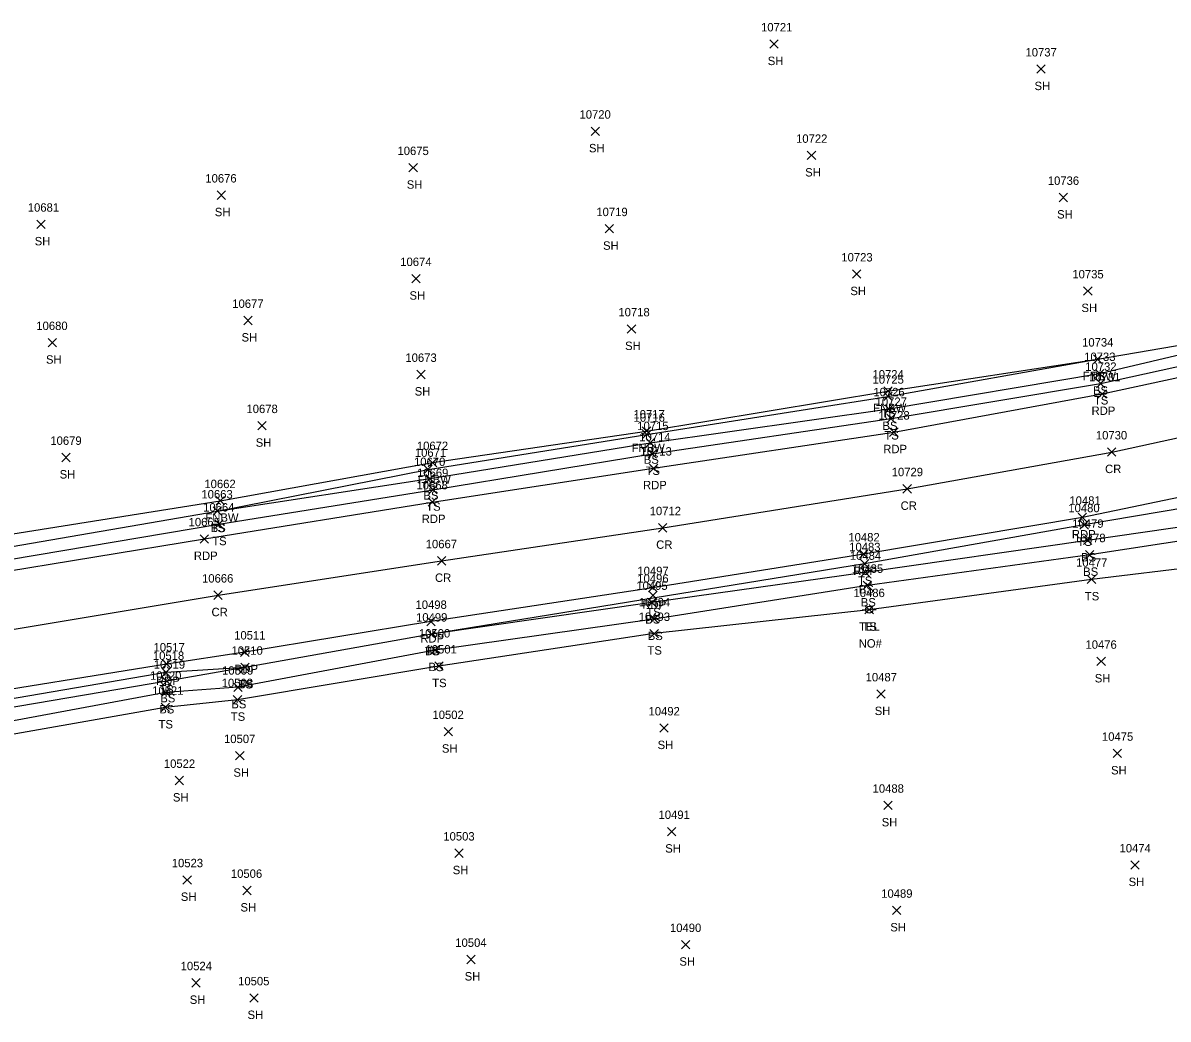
# Model space of a CAD drawing. Extents: x 1475671 to 1477951, y 592661 to 593821.
# Drawn here: x 1476066.9 to 1476339, y 592892.8 to 593129.6 of the extents above; entities that cross this region are included whole.
import ezdxf

# ---------------------------------------------------------------- set-up
doc = ezdxf.new("R2010")
doc.units = 0
for name, color, linetype in [('L_A', 7, 'Continuous'), ('L_I', 7, 'Continuous'), ('L_TIC', 7, 'Continuous'), ('LELB', 7, 'Continuous'), ('LFNC', 7, 'Continuous'), ('P_A', 7, 'Continuous'), ('P_I', 7, 'Continuous'), ('P_TIC', 7, 'Continuous'), ('PET', 7, 'Continuous'), ('PRC', 7, 'Continuous'), ('U_A', 7, 'Continuous'), ('U_C', 7, 'Continuous'), ('U_I', 7, 'Continuous'), ('UP', 7, 'Continuous')]:
    doc.layers.add(name, color=color, linetype=linetype)

msp = doc.modelspace()

# ---------------------------------------------------------------- linework, layer by layer
at = {"layer": 'L_TIC'}
for points in [[(1476244.39, 593123.56), (1476246.39, 593125.56)], [(1476246.39, 593123.56), (1476244.39, 593125.56)], [(1476307.77, 593117.61), (1476309.77, 593119.61)], [(1476309.77, 593117.61), (1476307.77, 593119.61)], [(1476201.91, 593102.83), (1476203.91, 593104.83)], [(1476203.91, 593102.83), (1476201.91, 593104.83)], [(1476253.28, 593097.09), (1476255.28, 593099.09)], [(1476255.28, 593097.09), (1476253.28, 593099.09)], [(1476158.63, 593094.18), (1476160.63, 593096.18)], [(1476160.63, 593094.18), (1476158.63, 593096.18)], [(1476113.04, 593087.65), (1476115.04, 593089.65)], [(1476115.04, 593087.65), (1476113.04, 593089.65)], [(1476313.13, 593087.1), (1476315.13, 593089.1)], [(1476315.13, 593087.1), (1476313.13, 593089.1)], [(1476070.23, 593080.72), (1476072.23, 593082.72)], [(1476072.23, 593080.72), (1476070.23, 593082.72)], [(1476205.27, 593079.67), (1476207.27, 593081.67)], [(1476207.27, 593079.67), (1476205.27, 593081.67)], [(1476159.29, 593067.81), (1476161.29, 593069.81)], [(1476161.29, 593067.81), (1476159.29, 593069.81)], [(1476264.02, 593068.89), (1476266.02, 593070.89)], [(1476266.02, 593068.89), (1476264.02, 593070.89)], [(1476318.92, 593064.87), (1476320.92, 593066.87)], [(1476320.92, 593064.87), (1476318.92, 593066.87)], [(1476119.38, 593057.86), (1476121.38, 593059.86)], [(1476121.38, 593057.86), (1476119.38, 593059.86)], [(1476210.5, 593055.85), (1476212.5, 593057.85)], [(1476212.5, 593055.85), (1476210.5, 593057.85)], [(1476072.92, 593052.6), (1476074.92, 593054.6)], [(1476074.92, 593052.6), (1476072.92, 593054.6)], [(1476321.23, 593048.67), (1476323.23, 593050.67)], [(1476323.23, 593048.67), (1476321.23, 593050.67)], [(1476321.23, 593048.67), (1476323.23, 593050.67)], [(1476323.23, 593048.67), (1476321.23, 593050.67)], [(1476160.51, 593045.03), (1476162.51, 593047.03)], [(1476162.51, 593045.03), (1476160.51, 593047.03)], [(1476321.72, 593045.24), (1476323.72, 593047.24)], [(1476323.72, 593045.24), (1476321.72, 593047.24)], [(1476321.97, 593042.9), (1476323.97, 593044.9)], [(1476323.97, 593042.9), (1476321.97, 593044.9)], [(1476271.43, 593041.08), (1476273.43, 593043.08)], [(1476273.43, 593041.08), (1476271.43, 593043.08)], [(1476271.44, 593039.84), (1476273.44, 593041.84)], [(1476273.44, 593039.84), (1476271.44, 593041.84)], [(1476271.69, 593036.85), (1476273.69, 593038.85)], [(1476273.69, 593036.85), (1476271.69, 593038.85)], [(1476272.17, 593034.57), (1476274.17, 593036.57)], [(1476274.17, 593034.57), (1476272.17, 593036.57)], [(1476122.74, 593032.86), (1476124.74, 593034.86)], [(1476124.74, 593032.86), (1476122.74, 593034.86)], [(1476214.07, 593031.59), (1476216.07, 593033.59)], [(1476216.07, 593031.59), (1476214.07, 593033.59)], [(1476214.16, 593030.8), (1476216.16, 593032.8)], [(1476216.16, 593030.8), (1476214.16, 593032.8)], [(1476214.98, 593028.82), (1476216.98, 593030.82)], [(1476216.98, 593028.82), (1476214.98, 593030.82)], [(1476215.45, 593026.16), (1476217.45, 593028.16)], [(1476217.45, 593026.16), (1476215.45, 593028.16)], [(1476076.16, 593025.31), (1476078.16, 593027.31)], [(1476078.16, 593025.31), (1476076.16, 593027.31)], [(1476163.23, 593024.08), (1476165.23, 593026.08)], [(1476165.23, 593024.08), (1476163.23, 593026.08)], [(1476162.19, 593022.46), (1476164.19, 593024.46)], [(1476164.19, 593022.46), (1476162.19, 593024.46)], [(1476162.64, 593020.28), (1476164.64, 593022.28)], [(1476164.64, 593020.28), (1476162.64, 593022.28)], [(1476163.33, 593017.66), (1476165.33, 593019.66)], [(1476165.33, 593017.66), (1476163.33, 593019.66)], [(1476112.81, 593015.03), (1476114.81, 593017.03)], [(1476114.81, 593015.03), (1476112.81, 593017.03)], [(1476112.1, 593012.57), (1476114.1, 593014.57)], [(1476114.1, 593012.57), (1476112.1, 593014.57)], [(1476112.1, 593012.57), (1476114.1, 593014.57)], [(1476114.1, 593012.57), (1476112.1, 593014.57)], [(1476112.5, 593009.46), (1476114.5, 593011.46)], [(1476114.5, 593009.46), (1476112.5, 593011.46)], [(1476318.05, 593009.3), (1476320.05, 593011.3)], [(1476320.05, 593009.3), (1476318.05, 593011.3)], [(1476318.88, 593005.6), (1476320.88, 593007.6)], [(1476320.88, 593005.6), (1476318.88, 593007.6)], [(1476319.37, 593002.18), (1476321.37, 593004.18)], [(1476321.37, 593002.18), (1476319.37, 593004.18)], [(1476265.9, 593000.04), (1476267.9, 593002.04)], [(1476267.9, 593000.04), (1476265.9, 593002.04)], [(1476266.05, 592997.99), (1476268.05, 592999.99)], [(1476268.05, 592997.99), (1476266.05, 592999.99)], [(1476319.8, 592996.35), (1476321.8, 592998.35)], [(1476321.8, 592996.35), (1476319.8, 592998.35)], [(1476266.54, 592994.9), (1476268.54, 592996.9)], [(1476268.54, 592994.9), (1476266.54, 592996.9)], [(1476215.33, 592990.85), (1476217.33, 592992.85)], [(1476217.33, 592990.85), (1476215.33, 592992.85)], [(1476215.62, 592992.55), (1476217.62, 592994.55)], [(1476217.62, 592992.55), (1476215.62, 592994.55)], [(1476266.98, 592989.13), (1476268.98, 592991.13)], [(1476268.98, 592989.13), (1476266.98, 592991.13)], [(1476215.93, 592986.92), (1476217.93, 592988.92)], [(1476217.93, 592986.92), (1476215.93, 592988.92)], [(1476163.01, 592983.31), (1476165.01, 592985.31)], [(1476165.01, 592983.31), (1476163.01, 592985.31)], [(1476163.01, 592983.31), (1476165.01, 592985.31)], [(1476165.01, 592983.31), (1476163.01, 592985.31)], [(1476215.9, 592983.46), (1476217.9, 592985.46)], [(1476217.9, 592983.46), (1476215.9, 592985.46)], [(1476163.84, 592979.53), (1476165.84, 592981.53)], [(1476165.84, 592979.53), (1476163.84, 592981.53)], [(1476322.08, 592976.85), (1476324.08, 592978.85)], [(1476324.08, 592976.85), (1476322.08, 592978.85)], [(1476099.91, 592974.21), (1476101.91, 592976.21)], [(1476101.91, 592974.21), (1476099.91, 592976.21)], [(1476118.67, 592975.43), (1476120.67, 592977.43)], [(1476120.67, 592975.43), (1476118.67, 592977.43)], [(1476118.67, 592975.43), (1476120.67, 592977.43)], [(1476120.67, 592975.43), (1476118.67, 592977.43)], [(1476164.76, 592975.73), (1476166.76, 592977.73)], [(1476166.76, 592975.73), (1476164.76, 592977.73)], [(1476100.12, 592972.12), (1476102.12, 592974.12)], [(1476102.12, 592972.12), (1476100.12, 592974.12)], [(1476099.88, 592969.48), (1476101.88, 592971.48)], [(1476101.88, 592969.48), (1476099.88, 592971.48)], [(1476117, 592970.7), (1476119, 592972.7)], [(1476119, 592970.7), (1476117, 592972.7)], [(1476269.8, 592969.1), (1476271.8, 592971.1)], [(1476271.8, 592969.1), (1476269.8, 592971.1)], [(1476099.74, 592965.91), (1476101.74, 592967.91)], [(1476101.74, 592965.91), (1476099.74, 592967.91)], [(1476116.9, 592967.73), (1476118.9, 592969.73)], [(1476118.9, 592967.73), (1476116.9, 592969.73)], [(1476166.97, 592960.16), (1476168.97, 592962.16)], [(1476168.97, 592960.16), (1476166.97, 592962.16)], [(1476218.22, 592961.01), (1476220.22, 592963.01)], [(1476220.22, 592961.01), (1476218.22, 592963.01)], [(1476325.95, 592954.99), (1476327.95, 592956.99)], [(1476327.95, 592954.99), (1476325.95, 592956.99)], [(1476117.45, 592954.44), (1476119.45, 592956.44)], [(1476119.45, 592954.44), (1476117.45, 592956.44)], [(1476103.07, 592948.55), (1476105.07, 592950.55)], [(1476105.07, 592948.55), (1476103.07, 592950.55)], [(1476271.46, 592942.64), (1476273.46, 592944.64)], [(1476273.46, 592942.64), (1476271.46, 592944.64)], [(1476220.03, 592936.41), (1476222.03, 592938.41)], [(1476222.03, 592936.41), (1476220.03, 592938.41)], [(1476169.55, 592931.28), (1476171.55, 592933.28)], [(1476171.55, 592931.28), (1476169.55, 592933.28)], [(1476330.12, 592928.46), (1476332.12, 592930.46)], [(1476332.12, 592928.46), (1476330.12, 592930.46)], [(1476104.95, 592924.93), (1476106.95, 592926.93)], [(1476106.95, 592924.93), (1476104.95, 592926.93)], [(1476119.14, 592922.41), (1476121.14, 592924.41)], [(1476121.14, 592922.41), (1476119.14, 592924.41)], [(1476273.5, 592917.68), (1476275.5, 592919.68)], [(1476275.5, 592917.68), (1476273.5, 592919.68)], [(1476223.4, 592909.54), (1476225.4, 592911.54)], [(1476225.4, 592909.54), (1476223.4, 592911.54)], [(1476172.39, 592906.01), (1476174.39, 592908.01)], [(1476174.39, 592906.01), (1476172.39, 592908.01)], [(1476107.07, 592900.46), (1476109.07, 592902.46)], [(1476109.07, 592900.46), (1476107.07, 592902.46)], [(1476120.8, 592896.87), (1476122.8, 592898.87)], [(1476122.8, 592896.87), (1476120.8, 592898.87)]]:
    msp.add_lwpolyline(points, dxfattribs=at)
at = {"layer": 'LELB'}
for points in [[(1475681.97, 592926.29), (1475693.99, 592930.92), (1475717.71, 592935.95), (1475764.49, 592948.74), (1475792.84, 592955.38), (1475826.76, 592965.2), (1475839.14, 592967.57), (1475847.44, 592968.45), (1475896, 592975.83), (1475948.75, 592985.5), (1475992.67, 592993.57), (1476057.44, 593003.96), (1476113.1, 593013.57), (1476163.64, 593021.28), (1476215.98, 593029.82), (1476272.69, 593037.85), (1476322.72, 593046.24), (1476372.45, 593058.02), (1476374.59, 593060.62), (1476398.56, 593065.83), (1476415.47, 593071.31), (1476457.34, 593084.84)], [(1476656.72, 593061.12), (1476648.18, 593059.88), (1476630.02, 593056.59), (1476594.66, 593048.99), (1476557.23, 593045.74), (1476521.08, 593042.35), (1476462.84, 593033.95), (1476419.94, 593027.86), (1476367.81, 593018.54), (1476319.05, 593010.3), (1476266.9, 593001.04), (1476164.01, 592984.31)], [(1475681.68, 592929.89), (1475693.99, 592930.92), (1475717.95, 592934.41), (1475766.45, 592946.03), (1475793.6, 592952.64), (1475827.75, 592961.96), (1475839.66, 592963.32), (1475897.61, 592972.89), (1475949.51, 592982.21), (1475996.32, 592990.67), (1476057.58, 593001.03), (1476113.5, 593010.46), (1476164.33, 593018.66), (1476216.45, 593027.16), (1476273.17, 593035.57), (1476322.97, 593043.9), (1476372.64, 593054.79), (1476374.63, 593058.12)], [(1476113.1, 593013.57), (1476163.19, 593023.46), (1476215.16, 593031.8), (1476272.44, 593040.84), (1476322.23, 593049.67)], [(1476521.14, 593041.18), (1476464.22, 593030.64), (1476420.77, 593020.64), (1476368.55, 593014.29), (1476359.82, 593012.38), (1476319.88, 593006.6), (1476267.05, 592998.99), (1476216.33, 592991.85), (1476164.01, 592984.31), (1476119.67, 592976.43), (1476101.12, 592973.12), (1476050.25, 592964.51), (1475994.64, 592956.24), (1475948.73, 592947.98), (1475899.49, 592939.5), (1475855.9, 592931.1), (1475802.57, 592920.15), (1475791.75, 592916.74), (1475792.51, 592914.78)], [(1476534.65, 593028.56), (1476525.69, 593019.5), (1476511.54, 593017.85), (1476467.31, 593015.01), (1476422.73, 593008.46), (1476366.85, 593001.28), (1476356.63, 592997.77), (1476347.04, 593000.45), (1476320.8, 592997.35), (1476267.98, 592990.13), (1476216.9, 592984.46), (1476165.76, 592976.73), (1476117.9, 592968.73), (1476100.74, 592966.91), (1476051.72, 592958.25), (1475996.01, 592950.36), (1475948.39, 592939), (1475900.82, 592931.75), (1475857.92, 592923.91), (1475803.59, 592912.34), (1475790.59, 592904.71)], [(1476511.04, 593028.14), (1476465.56, 593023.07), (1476421.22, 593014.7), (1476366.44, 593009.67), (1476355.54, 593008.55), (1476320.37, 593003.18), (1476267.54, 592995.9), (1476216.93, 592987.92), (1476164.84, 592980.53), (1476118, 592971.7), (1476100.88, 592970.48), (1476050.95, 592961.21), (1475995.34, 592954.17), (1475949.24, 592944.73), (1475901.01, 592937.79), (1475856.17, 592929.37), (1475802.39, 592917.73), (1475792.51, 592914.78)], [(1476119.67, 592976.43), (1476100.91, 592975.21), (1476049.54, 592966.45), (1475994.72, 592957.82), (1475948.15, 592950.07), (1475899.13, 592941.1), (1475855.65, 592932.47), (1475802.49, 592921.46), (1475788.48, 592918.16)]]:
    msp.add_lwpolyline(points, dxfattribs=at)
at = {"layer": 'LFNC'}
msp.add_lwpolyline([(1475680.63, 592937.28), (1475715.61, 592943.34), (1475763.84, 592955.14), (1475791.92, 592961.08), (1475824.89, 592967.76), (1475839.13, 592970.46), (1475847.47, 592971.97), (1475895.02, 592980.45), (1475948.31, 592989.25), (1475993.78, 592996.67), (1476056.99, 593006.94), (1476113.81, 593016.03), (1476164.23, 593025.08), (1476215.07, 593032.59), (1476272.43, 593042.08), (1476322.23, 593049.67), (1476368.09, 593057.49), (1476372.45, 593058.02), (1476374.63, 593058.12), (1476399.83, 593064.01), (1476415.89, 593069.22), (1476458.99, 593083.01), (1476499.73, 593099.84)], dxfattribs=at)
at = {"layer": 'P_TIC'}
for points in [[(1476322.32, 593040.42), (1476324.32, 593042.42)], [(1476324.32, 593040.42), (1476322.32, 593042.42)], [(1476272.83, 593031.32), (1476274.83, 593033.32)], [(1476274.83, 593031.32), (1476272.83, 593033.32)], [(1476324.59, 593026.6), (1476326.59, 593028.6)], [(1476326.59, 593026.6), (1476324.59, 593028.6)], [(1476215.75, 593022.76), (1476217.75, 593024.76)], [(1476217.75, 593022.76), (1476215.75, 593024.76)], [(1476276, 593017.86), (1476278, 593019.86)], [(1476278, 593017.86), (1476276, 593019.86)], [(1476163.18, 593014.73), (1476165.18, 593016.73)], [(1476165.18, 593014.73), (1476163.18, 593016.73)], [(1476317.64, 593011.07), (1476319.64, 593013.07)], [(1476319.64, 593011.07), (1476317.64, 593013.07)], [(1476217.93, 593008.6), (1476219.93, 593010.6)], [(1476219.93, 593008.6), (1476217.93, 593010.6)], [(1476109.05, 593005.96), (1476111.05, 593007.96)], [(1476111.05, 593005.96), (1476109.05, 593007.96)], [(1476265.69, 593002.36), (1476267.69, 593004.36)], [(1476267.69, 593002.36), (1476265.69, 593004.36)], [(1476165.39, 593000.74), (1476167.39, 593002.74)], [(1476167.39, 593000.74), (1476165.39, 593002.74)], [(1476215.58, 592994.35), (1476217.58, 592996.35)], [(1476217.58, 592994.35), (1476215.58, 592996.35)], [(1476112.3, 592992.58), (1476114.3, 592994.58)], [(1476114.3, 592992.58), (1476112.3, 592994.58)], [(1476162.86, 592986.33), (1476164.86, 592988.33)], [(1476164.86, 592986.33), (1476162.86, 592988.33)], [(1476118.65, 592979.05), (1476120.65, 592981.05)], [(1476120.65, 592979.05), (1476118.65, 592981.05)], [(1476100.05, 592976.22), (1476102.05, 592978.22)], [(1476102.05, 592976.22), (1476100.05, 592978.22)]]:
    msp.add_lwpolyline(points, dxfattribs=at)
at = {"layer": 'PET'}
for points in [[(1475682.06, 592924.71), (1475717.58, 592931.68), (1475766.32, 592943.31), (1475794.98, 592949.79), (1475825.77, 592956.33), (1475844.1, 592960.26), (1475899.54, 592970.95), (1475949.72, 592980.21), (1475996.45, 592988.43), (1476057.84, 592998.4), (1476110.05, 593006.96), (1476164.18, 593015.73), (1476216.75, 593023.76), (1476273.83, 593032.32), (1476323.32, 593041.42), (1476373.65, 593052.29), (1476409.24, 593061.35), (1476416.16, 593063.9), (1476459.25, 593078.48), (1476508.39, 593100.17)], [(1476521.33, 593044.37), (1476462.5, 593038.2), (1476408.69, 593032.05), (1476367.34, 593022.2), (1476318.64, 593012.07), (1476266.69, 593003.36), (1476216.58, 592995.35), (1476163.86, 592987.33), (1476119.65, 592980.05), (1476101.05, 592977.22), (1476048.95, 592968.83), (1475997.04, 592960.32), (1475947.8, 592951.63), (1475898.72, 592942.8), (1475855.26, 592933.74), (1475801.94, 592923.33), (1475788.88, 592919.68), (1475771.17, 592916.5), (1475722.69, 592905.51), (1475685.82, 592897.63)]]:
    msp.add_lwpolyline(points, dxfattribs=at)
at = {"layer": 'PRC'}
msp.add_lwpolyline([(1475683.62, 592911.01), (1475719.65, 592918.7), (1475759.33, 592927.39), (1475790.86, 592934.39), (1475834.03, 592943.87), (1475901.67, 592957.18), (1475953.57, 592967.02), (1476000.12, 592975.16), (1476059.54, 592984.65), (1476113.3, 592993.58), (1476166.39, 593001.74), (1476218.93, 593009.6), (1476277, 593018.86), (1476325.59, 593027.6), (1476377.06, 593038.84), (1476415.44, 593049.14), (1476421.8, 593050.95), (1476461.98, 593064.62), (1476520.7, 593090.52)], dxfattribs=at)
at = {"layer": 'UP'}
for p, q in [((1476266.32, 592990.12), (1476267.15, 592990.12)), ((1476267.98, 592990.13), (1476267.98, 592990.13)), ((1476269.65, 592990.13), (1476268.81, 592990.13)), ((1476268.81, 592990.13), (1476268.81, 592990.13)), ((1476269.65, 592990.13), (1476269.65, 592990.13))]:
    msp.add_line(p, q, dxfattribs=at)
msp.add_circle((1476267.98, 592990.13), 0.833, dxfattribs=at)

# ---------------------------------------------------------------- texts
at = {"layer": 'L_A'}
for s, p in [('SH', (1476243.88, 593119.56)), ('SH', (1476307.26, 593113.61)), ('SH', (1476201.4, 593098.83)), ('SH', (1476252.77, 593093.09)), ('SH', (1476158.12, 593090.18)), ('SH', (1476112.52, 593083.65)), ('SH', (1476312.62, 593083.1)), ('SH', (1476069.72, 593076.72)), ('SH', (1476204.75, 593075.67)), ('SH', (1476158.77, 593063.81)), ('SH', (1476263.51, 593064.89)), ('SH', (1476318.41, 593060.87)), ('SH', (1476118.87, 593053.86)), ('SH', (1476209.99, 593051.85)), ('SH', (1476072.4, 593048.6)), ('FNBW', (1476318.71, 593044.67)), ('TS', (1476320.64, 593044.67)), ('SH', (1476160, 593041.03)), ('BS', (1476321.16, 593041.24)), ('FNBW', (1476268.91, 593037.08)), ('TS', (1476321.38, 593038.9)), ('TS', (1476270.85, 593035.84)), ('BS', (1476271.13, 593032.85)), ('SH', (1476122.23, 593028.86)), ('TS', (1476271.58, 593030.57)), ('FNBW', (1476211.54, 593027.59)), ('TS', (1476213.57, 593026.8)), ('BS', (1476214.43, 593024.82)), ('SH', (1476075.65, 593021.31)), ('FNBW', (1476160.71, 593020.08)), ('TS', (1476214.86, 593022.16)), ('TS', (1476161.6, 593018.46)), ('BS', (1476162.08, 593016.28)), ('TS', (1476162.74, 593013.66)), ('FNBW', (1476110.28, 593011.03)), ('TS', (1476111.51, 593008.57)), ('BS', (1476111.54, 593008.57)), ('TS', (1476111.91, 593005.46)), ('TS', (1476317.46, 593005.3)), ('BS', (1476318.32, 593001.6)), ('BS', (1476318.81, 592998.18)), ('TS', (1476265.31, 592996.04)), ('BS', (1476265.49, 592993.99)), ('BS', (1476265.98, 592990.9)), ('TS', (1476319.21, 592992.35)), ('TS', (1476215.03, 592988.55)), ('BS', (1476214.77, 592986.85)), ('TS', (1476266.39, 592985.13)), ('BS', (1476215.37, 592982.92)), ('TS', (1476162.41, 592979.31)), ('BS', (1476162.45, 592979.31)), ('TS', (1476215.31, 592979.46)), ('BS', (1476163.28, 592975.53)), ('TS', (1476118.08, 592971.43)), ('BS', (1476118.11, 592971.43)), ('TS', (1476164.17, 592971.73)), ('SH', (1476321.57, 592972.85)), ('TS', (1476099.32, 592970.21)), ('BS', (1476099.56, 592968.12)), ('BS', (1476116.44, 592966.7)), ('BS', (1476099.32, 592965.48)), ('TS', (1476116.31, 592963.73)), ('SH', (1476269.29, 592965.1)), ('TS', (1476099.15, 592961.91)), ('SH', (1476166.46, 592956.16)), ('SH', (1476217.71, 592957.01)), ('SH', (1476116.94, 592950.44)), ('SH', (1476325.44, 592950.99)), ('SH', (1476102.56, 592944.55)), ('SH', (1476270.95, 592938.64)), ('SH', (1476219.52, 592932.41)), ('SH', (1476169.04, 592927.28)), ('SH', (1476329.61, 592924.46)), ('SH', (1476104.44, 592920.93)), ('SH', (1476118.62, 592918.41)), ('SH', (1476272.99, 592913.68)), ('SH', (1476222.89, 592905.54)), ('SH', (1476171.88, 592902.01)), ('SH', (1476106.56, 592896.46)), ('SH', (1476120.29, 592892.87))]:
    msp.add_text(s, height=2, dxfattribs=at).set_placement(p)
at = {"layer": 'L_I'}
for s, p in [('10721', (1476242.29, 593127.56)), ('10737', (1476305.11, 593121.61)), ('10720', (1476199.15, 593106.83)), ('10722', (1476250.61, 593101.09)), ('10675', (1476155.91, 593098.18)), ('10676', (1476110.26, 593091.65)), ('10736', (1476310.41, 593091.1)), ('10681', (1476068.08, 593084.72)), ('10719', (1476203.16, 593083.67)), ('10674', (1476156.57, 593071.81)), ('10723', (1476261.36, 593072.89)), ('10735', (1476316.25, 593068.87)), ('10677', (1476116.66, 593061.86)), ('10718', (1476208.4, 593059.85)), ('10680', (1476070.11, 593056.6)), ('10734', (1476318.56, 593052.67)), ('10734', (1476318.56, 593052.67)), ('10673', (1476157.79, 593049.03)), ('10733', (1476319.05, 593049.24)), ('10724', (1476268.76, 593045.08)), ('10732', (1476319.31, 593046.9)), ('10725', (1476268.77, 593043.84)), ('10726', (1476268.97, 593040.85)), ('10678', (1476120.03, 593036.86)), ('10727', (1476269.5, 593038.57)), ('10717', (1476211.97, 593035.59)), ('10716', (1476212.01, 593034.8)), ('10715', (1476212.88, 593032.82)), ('10679', (1476073.44, 593029.31)), ('10714', (1476213.35, 593030.16)), ('10671', (1476160.04, 593026.46)), ('10672', (1476160.52, 593028.08)), ('10670', (1476159.84, 593024.28)), ('10669', (1476160.56, 593021.66)), ('10662', (1476110.04, 593019.03)), ('10663', (1476109.33, 593016.57)), ('10663', (1476109.33, 593016.57)), ('10664', (1476109.74, 593013.46)), ('10480', (1476315.29, 593013.3)), ('10479', (1476316.21, 593009.6)), ('10483', (1476263.23, 593004.04)), ('10478', (1476316.7, 593006.18)), ('10484', (1476263.38, 593001.99)), ('10485', (1476263.87, 592998.9)), ('10477', (1476317.13, 593000.35)), ('10496', (1476212.89, 592996.55)), ('10495', (1476212.66, 592994.85)), ('10486', (1476264.25, 592993.13)), ('10494', (1476213.26, 592990.92)), ('10499', (1476160.33, 592987.31)), ('10499', (1476160.33, 592987.31)), ('10493', (1476213.23, 592987.46)), ('10500', (1476161.01, 592983.53)), ('10510', (1476116.48, 592979.43)), ('10510', (1476116.48, 592979.43)), ('10501', (1476162.58, 592979.73)), ('10476', (1476319.36, 592980.85)), ('10518', (1476097.8, 592978.21)), ('10519', (1476098.01, 592976.12)), ('10509', (1476114.24, 592974.7)), ('10520', (1476097.13, 592973.48)), ('10508', (1476114.15, 592971.73)), ('10487', (1476267.14, 592973.1)), ('10521', (1476097.63, 592969.91)), ('10502', (1476164.22, 592964.16)), ('10492', (1476215.55, 592965.01)), ('10507', (1476114.7, 592958.44)), ('10475', (1476323.28, 592958.99)), ('10522', (1476100.41, 592952.55)), ('10488', (1476268.79, 592946.64)), ('10491', (1476217.93, 592940.41)), ('10503', (1476166.8, 592935.28)), ('10474', (1476327.45, 592932.46)), ('10523', (1476102.29, 592928.93)), ('10506', (1476116.33, 592926.41)), ('10489', (1476270.83, 592921.68)), ('10490', (1476220.65, 592913.54)), ('10504', (1476169.64, 592910.01)), ('10524', (1476104.4, 592904.46)), ('10505', (1476118.05, 592900.87))]:
    msp.add_text(s, height=2, dxfattribs=at).set_placement(p)
at = {"layer": 'P_A'}
for s, p in [('RDP', (1476320.81, 593036.42)), ('RDP', (1476271.32, 593027.32)), ('CR', (1476324.02, 593022.6)), ('RDP', (1476214.24, 593018.76)), ('CR', (1476275.44, 593013.86)), ('RDP', (1476161.67, 593010.73)), ('RDP', (1476316.13, 593007.07)), ('CR', (1476217.37, 593004.6)), ('RDP', (1476107.54, 593001.96)), ('RDP', (1476264.18, 592998.36)), ('CR', (1476164.82, 592996.74)), ('RDP', (1476214.07, 592990.35)), ('CR', (1476111.73, 592988.58)), ('RDP', (1476161.35, 592982.33)), ('RDP', (1476117.13, 592975.05)), ('RDP', (1476098.54, 592972.22))]:
    msp.add_text(s, height=2, dxfattribs=at).set_placement(p)
at = {"layer": 'P_I'}
for s, p in [('10731', (1476320.22, 593044.42)), ('10728', (1476270.16, 593035.32)), ('10730', (1476321.83, 593030.6)), ('10713', (1476213.65, 593026.76)), ('10729', (1476273.33, 593021.86)), ('10668', (1476160.42, 593018.73)), ('10481', (1476315.54, 593015.07)), ('10712', (1476215.83, 593012.6)), ('10665', (1476106.29, 593009.96)), ('10482', (1476263.03, 593006.36)), ('10667', (1476162.62, 593004.74)), ('10497', (1476212.91, 592998.35)), ('10666', (1476109.48, 592996.58)), ('10498', (1476160.19, 592990.33)), ('10511', (1476117.11, 592983.05)), ('10517', (1476097.95, 592980.22))]:
    msp.add_text(s, height=2, dxfattribs=at).set_placement(p)
at = {"layer": 'U_A'}
msp.add_text('TEL', height=2, dxfattribs=at).set_placement((1476265.54, 592985.13))
at = {"layer": 'U_C'}
msp.add_text('NO#', height=2, dxfattribs=at).set_placement((1476265.49, 592981.13))
at = {"layer": 'U_I'}
msp.add_text('10486', height=2, dxfattribs=at).set_placement((1476264.25, 592993.13))

doc.saveas('drawing.dxf')
